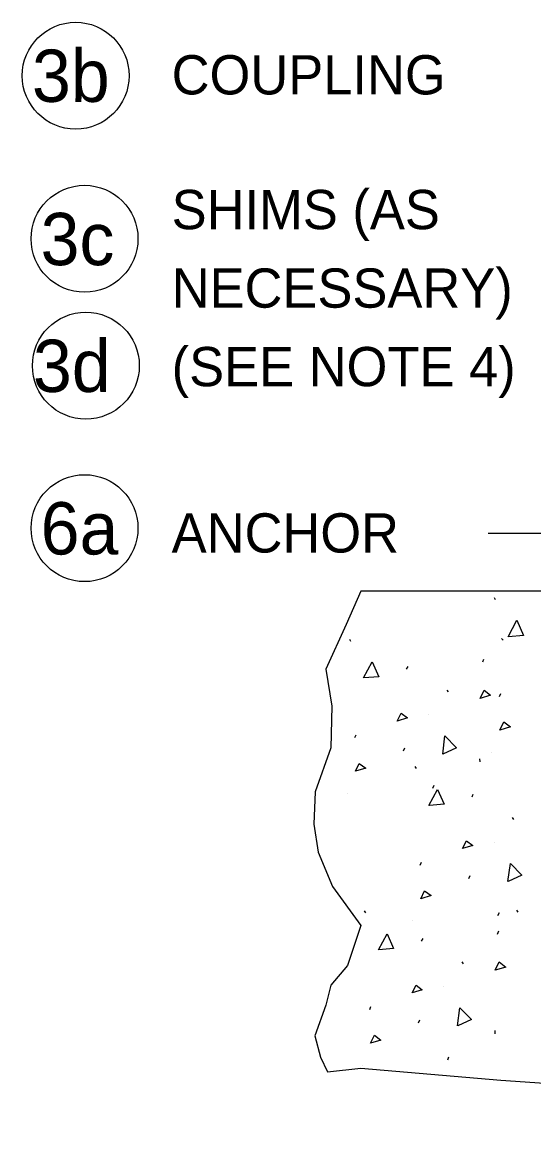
# Model space of a CAD drawing. Extents: x 12.3 to 19.6, y 18.8 to 29.6.
# Drawn here: x 12.702 to 13.484, y 21.66 to 23.362 of the extents above; entities that cross this region are included whole.
import ezdxf

# ---------------------------------------------------------------- set-up
doc = ezdxf.new("R2010")
doc.units = 0
for name, color, linetype in [('BORD-LINE', 7, 'Continuous'), ('DETL-DIMS', 7, 'Continuous'), ('DETL-LINE', 7, 'Continuous'), ('DETL-PATT', 7, 'Continuous')]:
    doc.layers.add(name, color=color, linetype=linetype)

msp = doc.modelspace()

# ---------------------------------------------------------------- linework, layer by layer
at = {"layer": 'BORD-LINE'}
for centre in [(12.7837, 23.28), (12.7973, 23.0308), (12.7993, 22.8369), (12.7973, 22.5886)]:
    msp.add_circle(centre, 0.0817, dxfattribs=at)
at = {"layer": 'DETL-DIMS'}
msp.add_lwpolyline([(13.4145, 22.5809), (13.5572, 22.5809), (13.954, 22.1085)], dxfattribs=at)
at = {"layer": 'DETL-LINE'}
msp.add_line((13.9456, 22.4922), (13.2197, 22.4922), dxfattribs=at)
for points in [[(13.2197, 22.4922), (13.1975, 22.4412), (13.1664, 22.3729), (13.1754, 22.3165), (13.1741, 22.253), (13.1502, 22.1859), (13.1477, 22.1361), (13.1544, 22.0935), (13.1765, 22.0408), (13.2197, 21.9815)], [(13.2197, 21.9815), (13.1994, 21.9203), (13.1741, 21.8903), (13.1664, 21.8598), (13.1496, 21.813), (13.158, 21.78), (13.1687, 21.7579), (13.2197, 21.7633)], [(13.2197, 21.7633), (13.4337, 21.7453), (13.604, 21.7333), (13.7496, 21.6908), (13.9138, 21.6788), (14.0415, 21.7028), (14.1931, 21.7213), (14.4425, 21.7273), (14.6739, 21.6968), (14.8375, 21.6601), (15.0569, 21.7028), (15.1421, 21.7519), (15.2451, 21.783)]]:
    msp.add_lwpolyline(points, dxfattribs=at)
at = {"layer": 'DETL-PATT'}
for p, q in [((13.4235, 22.4826), (13.4253, 22.4796)), ((13.2023, 22.4191), (13.2041, 22.4161)), ((13.4349, 22.4202), (13.4373, 22.4172)), ((13.2898, 22.3729), (13.2923, 22.3771)), ((13.4062, 22.3843), (13.4079, 22.3884)), ((13.3515, 22.3411), (13.3534, 22.3387)), ((13.4319, 22.3315), (13.4337, 22.3357)), ((13.3234, 22.3033), (13.3234, 22.3033)), ((13.2107, 22.2685), (13.2125, 22.2728)), ((13.285, 22.2482), (13.2869, 22.253)), ((13.4199, 22.2464), (13.4199, 22.2464)), ((13.3024, 22.2242), (13.3043, 22.2213)), ((13.4013, 22.2362), (13.4019, 22.2314)), ((13.33, 22.1913), (13.3318, 22.196)), ((13.1994, 22.1835), (13.1994, 22.1835)), ((13.3899, 22.178), (13.3917, 22.1823)), ((13.4511, 22.1463), (13.4534, 22.1433)), ((13.4235, 22.1085), (13.4235, 22.1085)), ((13.3108, 22.0737), (13.3126, 22.078)), ((13.3852, 22.0534), (13.3869, 22.0576)), ((13.2251, 22.0036), (13.2269, 22.0006)), ((13.4295, 21.9965), (13.4319, 22.0012)), ((13.4577, 22.0048), (13.4601, 22.0018)), ((13.2988, 21.9886), (13.2988, 21.9886)), ((13.4289, 21.9682), (13.4307, 21.9731)), ((13.3126, 21.9575), (13.315, 21.9617)), ((13.3743, 21.9257), (13.3762, 21.9227)), ((13.3462, 21.8879), (13.3462, 21.8879)), ((13.2335, 21.8532), (13.2353, 21.8574)), ((13.3078, 21.8328), (13.3102, 21.837)), ((13.4247, 21.8208), (13.4247, 21.816)), ((13.3528, 21.7759), (13.3545, 21.7807)), ((13.2221, 21.768), (13.2221, 21.768))]:
    msp.add_line(p, q, dxfattribs=at)
for points in [[(13.4451, 22.4226), (13.4583, 22.4478), (13.4684, 22.4244), (13.4457, 22.4226)], [(13.2239, 22.3597), (13.2371, 22.3843), (13.2473, 22.3614), (13.2245, 22.3597)], [(13.4025, 22.3285), (13.4085, 22.3411), (13.4181, 22.3333), (13.4025, 22.3285)], [(13.2754, 22.2938), (13.2814, 22.3058), (13.291, 22.2985), (13.2754, 22.2938)], [(13.4325, 22.2799), (13.4385, 22.2925), (13.4487, 22.2848), (13.4325, 22.2799)], [(13.345, 22.2434), (13.3485, 22.271), (13.3659, 22.253), (13.345, 22.2434)], [(13.2119, 22.217), (13.2173, 22.229), (13.2275, 22.2218), (13.2119, 22.217)], [(13.324, 22.1649), (13.3372, 22.1894), (13.3474, 22.1666), (13.3246, 22.1649)], [(13.3755, 22.099), (13.3815, 22.1109), (13.3912, 22.1037), (13.3755, 22.099)], [(13.4444, 22.0486), (13.4487, 22.0761), (13.4661, 22.0582), (13.4451, 22.0486)], [(13.3114, 22.0222), (13.3174, 22.0342), (13.3276, 22.027), (13.3114, 22.0222)], [(13.2466, 21.9443), (13.2599, 21.9688), (13.27, 21.9461), (13.2473, 21.9443)], [(13.4253, 21.9131), (13.4313, 21.9257), (13.4415, 21.9179), (13.4253, 21.9131)], [(13.2983, 21.8783), (13.3043, 21.8903), (13.3138, 21.8832), (13.2983, 21.8783)], [(13.3678, 21.828), (13.3714, 21.8556), (13.3888, 21.8376), (13.3684, 21.828)], [(13.2347, 21.8017), (13.2406, 21.8136), (13.2503, 21.8064), (13.2347, 21.8017)]]:
    msp.add_lwpolyline(points, dxfattribs=at)

# ---------------------------------------------------------------- texts
at = {"layer": 'BORD-LINE'}
for s, height, p in [('3b', 0.0799, (12.7169, 23.24)), ('COUPLING', 0.06, (12.9305, 23.2514)), ('SHIMS (AS', 0.06, (12.9305, 23.0455)), ('3c', 0.0799, (12.7301, 22.9905)), ('NECESSARY)', 0.06, (12.9305, 22.9255)), ('3d', 0.0799, (12.7184, 22.7967)), ('(SEE NOTE 4) ', 0.06, (12.9305, 22.8055)), ('6a', 0.0799, (12.7302, 22.5484)), ('ANCHOR', 0.06, (12.9305, 22.5513))]:
    msp.add_text(s, height=height, dxfattribs=at).set_placement(p)

doc.saveas('drawing.dxf')
